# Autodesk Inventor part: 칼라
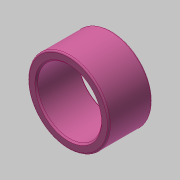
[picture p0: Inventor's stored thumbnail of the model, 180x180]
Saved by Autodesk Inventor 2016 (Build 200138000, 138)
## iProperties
Created: 2019-05
Part Number: 칼라
Material: 스테인리스강
Document SubType Name: Modeling
Designer: mduedu
Density: 1 g/cm^3
Appearance: 분홍색
Author: mduedu
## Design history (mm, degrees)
sketch "스케치1"
  geometry: C1 r 11 at (0, 0); C2 r 14 at (0, 0); 1 further point
  constraints: 2 centre point, 2 coincident
  dimensions: "d0" = 22 diameter of C1; "d1" = 28 diameter of C2
extrude "돌출1" new body sketch "스케치1" distance "d2" = 15; taper "d3" = 0 deg
fillet "모깎기1" dims "d4" = 0.5
chamfer "모따기1" distance "d5" = 0.5; stored, may be unused: second distance "d6" = 2, angle "d7" = 45 deg
node "솔리드1"
